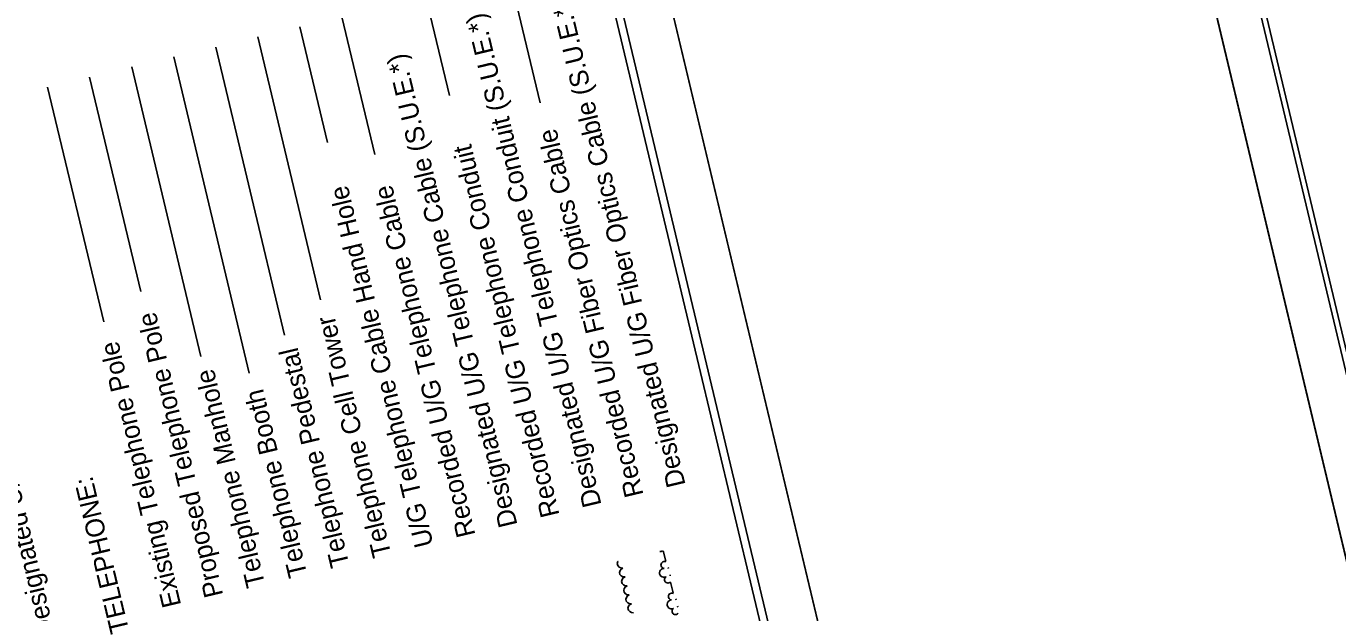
# Model space of a CAD drawing. Extents: x 1734738 to 1742883, y 698103 to 703125.
# Drawn here: x 1739145 to 1740359, y 700912 to 701455 of the extents above; entities that cross this region are included whole.
import ezdxf

# ---------------------------------------------------------------- set-up
doc = ezdxf.new("R2010")
doc.units = 0
for name, color, linetype in [('Exist Road Primary Interstate Shield CELL', 7, 'Continuous'), ('Exist Road Primary US Structure Standard Bridge Number Label', 7, 'Continuous'), ('Exist Road Secondary Structure Pipe Number Label', 7, 'Continuous'), ('Exist Road Secondary Type 41 SR Number Label', 7, 'Continuous'), ('Map Preparation County Base Positioning Point', 7, 'Continuous')]:
    doc.layers.add(name, color=color, linetype=linetype)

msp = doc.modelspace()

# ---------------------------------------------------------------- linework, layer by layer
at = {"layer": 'Exist Road Primary Interstate Shield CELL'}
for p, q in [((1739592.4, 701500.7), (1739620.3, 701384)), ((1739514.6, 701482.2), (1739536.4, 701390.9)), ((1739436.8, 701463.7), (1739467.2, 701336.1)), ((1739397.9, 701454.4), (1739423.4, 701347.3)), ((1739359, 701445.1), (1739417.1, 701201.5)), ((1739281.2, 701426.6), (1739351, 701133.8)), ((1739320.1, 701435.8), (1739383.7, 701169)), ((1739242.3, 701417.3), (1739306.2, 701149.1)), ((1739203.3, 701408), (1739250.7, 701209.4)), ((1739164.4, 701398.7), (1739216.3, 701181.1)), ((1739736.5, 700959.5), (1739734.2, 700969.2)), ((1739691.7, 700957.3), (1739692.3, 700959.1)), ((1739692.1, 700955.5), (1739691.7, 700957.3)), ((1739693.4, 700954.1), (1739692.1, 700955.5)), ((1739692.3, 700959.1), (1739692.4, 700959.2)), ((1739694.9, 700953.3), (1739693.4, 700954.1)), ((1739694.3, 700950.9), (1739695.3, 700952.2)), ((1739696.9, 700953.1), (1739694.9, 700953.3)), ((1739695.3, 700952.2), (1739696.8, 700953)), ((1739739.1, 700952.8), (1739738.9, 700953.8)), ((1739693.7, 700949.1), (1739694.3, 700950.9)), ((1739694.1, 700947.2), (1739693.7, 700949.1)), ((1739695.3, 700945.9), (1739694.1, 700947.2)), ((1739696.9, 700945), (1739695.3, 700945.9)), ((1739695.6, 700940.8), (1739696.2, 700942.6)), ((1739696.1, 700938.9), (1739695.6, 700940.8)), ((1739696.2, 700942.6), (1739697.2, 700944)), ((1739698.9, 700944.9), (1739696.9, 700945)), ((1739697.2, 700944), (1739698.8, 700944.7)), ((1739740.7, 700946), (1739740.5, 700947)), ((1739743.5, 700930.3), (1739741.1, 700940)), ((1739697.3, 700937.6), (1739696.1, 700938.9)), ((1739698.9, 700936.7), (1739697.3, 700937.6)), ((1739697.6, 700932.5), (1739698.2, 700934.3)), ((1739698, 700930.7), (1739697.6, 700932.5)), ((1739699.3, 700929.3), (1739698, 700930.7)), ((1739698.2, 700934.3), (1739699.2, 700935.7)), ((1739700.8, 700936.6), (1739698.9, 700936.7)), ((1739699.2, 700935.7), (1739700.8, 700936.5)), ((1739700.8, 700928.5), (1739699.3, 700929.3)), ((1739700.2, 700926), (1739701.2, 700927.4)), ((1739702.8, 700928.3), (1739700.8, 700928.5)), ((1739701.2, 700927.4), (1739702.7, 700928.2)), ((1739699.6, 700924.3), (1739700.2, 700926)), ((1739700, 700922.4), (1739699.6, 700924.3)), ((1739701.3, 700921.1), (1739700, 700922.4)), ((1739702.8, 700920.2), (1739701.3, 700921.1)), ((1739701.5, 700916), (1739702.1, 700917.8)), ((1739702, 700914.1), (1739701.5, 700916)), ((1739702.1, 700917.8), (1739703.1, 700919.2)), ((1739704.8, 700920.1), (1739702.8, 700920.2)), ((1739703.1, 700919.2), (1739704.7, 700919.9)), ((1739746.1, 700923.6), (1739745.8, 700924.6)), ((1739747.7, 700916.8), (1739747.5, 700917.8)), ((1739703.2, 700912.8), (1739702, 700914.1)), ((1739704.8, 700911.9), (1739703.2, 700912.8)), ((1739706.8, 700911.8), (1739704.8, 700911.9))]:
    msp.add_line(p, q, dxfattribs=at)
msp.add_lwpolyline([(1737411.4, 701976.4), (1738106.9, 699058.2), (1740147.7, 699544.6), (1739452.2, 702462.8)], close=True, dxfattribs=at)
for centre, radius, start, end in [((1739731.5, 700971.6), 3.16, 259.6569, 307.1549), ((1739734.9, 700948.7), 4.12, 89.3697, 297.4422), ((1739735.3, 700956), 3.16, 64.1744, 264.971), ((1739738.5, 700942.4), 3.16, 121.8409, 322.6374), ((1739742.2, 700926.8), 3.16, 64.1744, 264.971), ((1739741.9, 700919.5), 4.12, 89.3697, 297.4422), ((1739745.5, 700913.2), 3.16, 121.8409, 322.6374)]:
    msp.add_arc(centre, radius, start, end, dxfattribs=at)
at = {"layer": 'Exist Road Primary US Structure Standard Bridge Number Label'}
for p, q in [((1739971.8, 702617), (1740752.4, 699341.7)), ((1740275.8, 699231.7), (1739494.9, 702508))]:
    msp.add_line(p, q, dxfattribs=at)
at = {"layer": 'Exist Road Secondary Structure Pipe Number Label'}
for points in [[(1742837.8, 699865.5), (1742065.3, 703106.7), (1740012.8, 702617.5), (1740785.3, 699376.3)], [(1740226.1, 699246.6), (1739453.3, 702488.8), (1737400.6, 701999.6), (1738173.4, 698757.4)]]:
    msp.add_lwpolyline(points, close=True, dxfattribs=at)
at = {"layer": 'Exist Road Secondary Type 41 SR Number Label'}
for points in [[(1742882.7, 699849.5), (1742102.1, 703124.7), (1739971.8, 702617), (1740752.4, 699341.7)], [(1740275.8, 699231.7), (1739494.9, 702508), (1737354.8, 701997.9), (1738135.7, 698721.7)]]:
    msp.add_lwpolyline(points, close=True, dxfattribs=at)
at = {"layer": 'Map Preparation County Base Positioning Point'}
msp.add_lwpolyline([(1740023.4, 702594.3), (1740719, 699676.1), (1742761.7, 700163), (1742066.2, 703081.2)], close=True, dxfattribs=at)

# ---------------------------------------------------------------- texts
at = {"layer": 'Exist Road Primary Interstate Shield CELL'}
for s, p in [('Designated U/G Fiber Optics Cable (S.U.E.*)', (1739755, 701030.2)), ('Designated U/G Telephone Conduit (S.U.E.*)', (1739677.2, 701011.7)), ('Designated U/G Telephone Cable (S.U.E.*)', (1739599.4, 700993.1)), ('Recorded U/G Fiber Optics Cable', (1739716.1, 701021)), ('Recorded U/G Telephone Conduit', (1739638.3, 701002.4)), ('U/G Telephone Cable Hand Hole', (1739521.6, 700974.6)), ('Recorded U/G Telephone Cable', (1739560.5, 700983.9)), ('Designated U/G Power Line (S.U.E.*)', (1739171.4, 700891.1)), ('Proposed Telephone Pole', (1739327, 700928.2)), ('Telephone Cell Tower', (1739482.7, 700965.3)), ('Existing Telephone Pole', (1739288.1, 700918.9)), ('Telephone Pedestal', (1739443.8, 700956)), ('Telephone Manhole', (1739365.9, 700937.5)), ('Telephone Booth', (1739404.9, 700946.7)), ('TELEPHONE:', (1739240, 700895))]:
    msp.add_text(s, height=17.5, rotation=103.4059, dxfattribs=at).set_placement(p)

doc.saveas('drawing.dxf')
